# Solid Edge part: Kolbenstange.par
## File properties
Username: ahadarics
Dokumentum tartalom típus: 0
Author: ahadarics
Last saved by: ahadarics
Revision: 84
Sűrűség: 0,000 kg/m^3
Pontosság: 0,990
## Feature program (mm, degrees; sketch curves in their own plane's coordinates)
base feature "unnamed BaseFeature 1"
thread "unnamed Thread 1"
chamfer "Letörés_1" setback 0.5
sketch for "Kihúzás_1" plane through (53.5, 0, 0) normal (1, 0, 0) x-axis (0, 0, 1)
  circle centre (0, 0) radius 8
extrude "Kihúzás_1" add finite 26.5 along -normal
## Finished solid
Body 1: solid body, 18 faces, 34 edges, 18 vertices.
  Faces by surface: plane 9, cone 7, cylinder 2
  Edges by curve: line 12, spline 12, circle 10
Bounding box of the edges (mm): 280.500 x 16.000 x 16.000, from (-227, -8, -8) to (53.5, 8, 8).
Cylindrical faces by radius (mm): R3 x1, R8 x1
Conical faces (half-angle, radius in mm at the cone's reference point): 30 deg R5.25 x6, 45 deg R2.5 x1
Planar faces by outward normal: +x 1, +y 1, -x 2, -y 1, oblique 4
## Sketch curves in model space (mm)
circle centre (53.5, 0, 0) radius 8
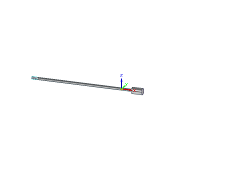
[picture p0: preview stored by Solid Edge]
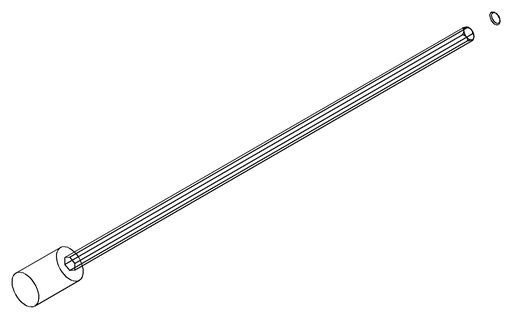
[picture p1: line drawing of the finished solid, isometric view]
